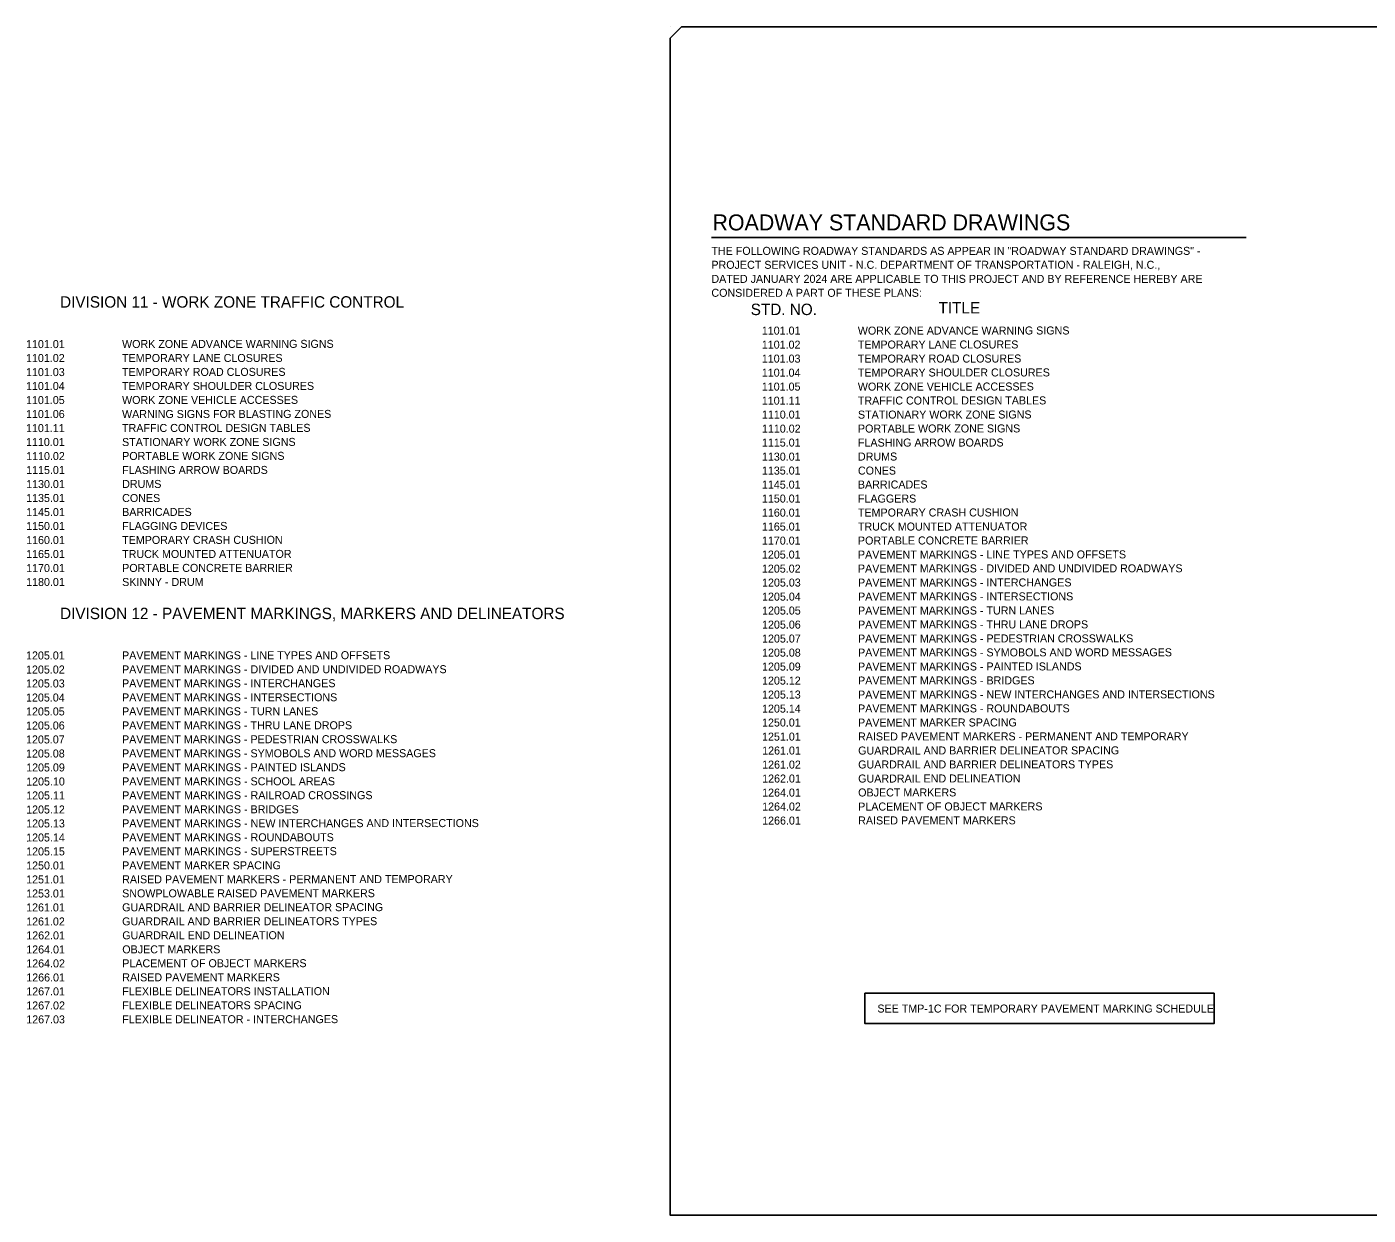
# Model space of a CAD drawing. Extents: x 2486454 to 2490507, y 369321 to 372999.
# Drawn here: x 2486454 to 2487627, y 370218 to 371258 of the extents above; entities that cross this region are included whole.
import ezdxf

# ---------------------------------------------------------------- set-up
doc = ezdxf.new("R2010")
doc.units = 0
for name, color, linetype in [('Scratch_Level_3', 7, 'Continuous'), ('TC SHEET BORDER LINE THIN', 7, 'Continuous'), ('TC SHEET LAYOUT SHAPE', 7, 'Continuous'), ('TC SHEET TEXT', 7, 'Continuous')]:
    doc.layers.add(name, color=color, linetype=linetype)

msp = doc.modelspace()

# ---------------------------------------------------------------- linework, layer by layer
at = {"layer": 'Scratch_Level_3'}
msp.add_line((2487016.6, 371258.3), (2487016.6, 371258.3), dxfattribs=at)
at = {"layer": 'TC SHEET BORDER LINE THIN'}
msp.add_line((2487052.9, 371074), (2487520.6, 371074), dxfattribs=at)
at = {"layer": 'TC SHEET LAYOUT SHAPE'}
msp.add_lwpolyline([(2487016.6, 370666.8), (2487016.6, 370976.2), (2487016.6, 371248.3), (2487026.6, 371258.3), (2487469.6, 371258.3), (2487940.6, 371258.3), (2488261.6, 371258.3), (2488261.6, 371178.3), (2488346.6, 371178.3), (2488346.6, 371226.3), (2488506.6, 371226.3), (2488506.6, 370891.3), (2488506.6, 370612.1), (2488506.6, 370360.8), (2487778.4, 370360.8), (2487778.4, 370218.3), (2487608.9, 370218.3), (2487256.1, 370218.3), (2487016.6, 370218.3)], close=True, dxfattribs=at)
at = {"layer": 'TC SHEET TEXT'}
msp.add_lwpolyline([(2487187, 370412.5), (2487492.4, 370412.5), (2487492.4, 370386), (2487187, 370386)], close=True, dxfattribs=at)

# ---------------------------------------------------------------- texts
for s, height, rotation, p in [('ROADWAY STANDARD DRAWINGS', 13.999, 0.0001, (2487053.6, 371080.1)), ('THE FOLLOWING ROADWAY STANDARDS AS APPEAR IN "ROADWAY STANDARD DRAWINGS" - ', 7, 0, (2487052.7, 371058.7)), ('PROJECT SERVICES UNIT - N.C. DEPARTMENT OF TRANSPORTATION - RALEIGH, N.C.,', 7, 0, (2487052.7, 371046.5)), ('DATED JANUARY 2024 ARE APPLICABLE TO THIS PROJECT AND BY REFERENCE HEREBY ARE', 7, 0, (2487052.7, 371034.2)), ('DIVISION 11 - WORK ZONE TRAFFIC CONTROL', 10, 0.0001, (2486482.9, 371012.5)), ('CONSIDERED A PART OF THESE PLANS:', 7, 0, (2487052.7, 371022)), ('STD. NO.', 10, 0.0001, (2487087.1, 371006)), ('TITLE', 10, 0.0001, (2487251.4, 371007.4)), ('1101.01', 7, 0.0403, (2487096.8, 370988.9)), ('WORK ZONE ADVANCE WARNING SIGNS', 7, 0.0403, (2487180.8, 370988.9)), ('1101.01', 7, 0.0403, (2486453.1, 370977.1)), ('WORK ZONE ADVANCE WARNING SIGNS', 7, 0.0403, (2486537.1, 370977.2)), ('1101.02', 7, 0.0403, (2487096.8, 370976.6)), ('TEMPORARY LANE CLOSURES', 7, 0.0403, (2487180.8, 370976.7)), ('1101.02', 7, 0.0403, (2486453.1, 370964.9)), ('TEMPORARY LANE CLOSURES', 7, 0.0403, (2486537.1, 370964.9)), ('1101.03', 7, 0.0403, (2487096.8, 370964.4)), ('TEMPORARY ROAD CLOSURES', 7, 0.0403, (2487180.8, 370964.4)), ('1101.03', 7, 0.0403, (2486453.1, 370952.6)), ('TEMPORARY ROAD CLOSURES', 7, 0.0403, (2486537.1, 370952.7)), ('1101.04', 7, 0.0403, (2487096.8, 370952.1)), ('TEMPORARY SHOULDER CLOSURES', 7, 0.0403, (2487180.8, 370952.2)), ('1101.04', 7, 0.0403, (2486453.1, 370940.4)), ('TEMPORARY SHOULDER CLOSURES', 7, 0.0403, (2486537.1, 370940.4)), ('1101.05', 7, 0.0403, (2487096.8, 370939.9)), ('WORK ZONE VEHICLE ACCESSES', 7, 0.0403, (2487180.8, 370939.9)), ('1101.05', 7, 0.0403, (2486453.1, 370928.1)), ('WORK ZONE VEHICLE ACCESSES', 7, 0.0403, (2486537.1, 370928.2)), ('1101.11', 7, 0.0403, (2487096.8, 370927.6)), ('TRAFFIC CONTROL DESIGN TABLES', 7, 0.0403, (2487180.8, 370927.7)), ('1101.06', 7, 0.0403, (2486453.1, 370915.9)), ('WARNING SIGNS FOR BLASTING ZONES', 7, 0.0403, (2486537.1, 370915.9)), ('1110.01', 7, 0.0403, (2487096.9, 370915.4)), ('STATIONARY WORK ZONE SIGNS', 7, 0.0403, (2487180.9, 370915.4)), ('1101.11', 7, 0.0403, (2486453.1, 370903.6)), ('TRAFFIC CONTROL DESIGN TABLES', 7, 0.0403, (2486537.1, 370903.7)), ('1110.02', 7, 0.0403, (2487096.9, 370903.1)), ('PORTABLE WORK ZONE SIGNS', 7, 0.0403, (2487180.9, 370903.2)), ('1110.01', 7, 0.0403, (2486453.1, 370891.4)), ('STATIONARY WORK ZONE SIGNS', 7, 0.0403, (2486537.1, 370891.4)), ('1115.01', 7, 0.0403, (2487096.9, 370890.9)), ('FLASHING ARROW BOARDS', 7, 0.0403, (2487180.9, 370890.9)), ('1110.02', 7, 0.0403, (2486453.2, 370879.1)), ('PORTABLE WORK ZONE SIGNS', 7, 0.0403, (2486537.2, 370879.2)), ('1130.01', 7, 0.0403, (2487096.9, 370878.6)), ('DRUMS ', 7, 0.0403, (2487180.9, 370878.7)), ('1115.01', 7, 0.0403, (2486453.2, 370866.9)), ('FLASHING ARROW BOARDS', 7, 0.0403, (2486537.2, 370866.9)), ('1135.01', 7, 0.0403, (2487096.9, 370866.4)), ('CONES', 7, 0.0403, (2487180.9, 370866.4)), ('1130.01', 7, 0.0403, (2486453.2, 370854.6)), ('DRUMS ', 7, 0.0403, (2486537.2, 370854.7)), ('1145.01', 7, 0.0403, (2487096.9, 370854.1)), ('BARRICADES', 7, 0.0403, (2487180.9, 370854.2)), ('1135.01', 7, 0.0403, (2486453.2, 370842.4)), ('CONES', 7, 0.0403, (2486537.2, 370842.4)), ('1150.01', 7, 0.0403, (2487096.9, 370841.9)), ('FLAGGERS', 7, 0.0403, (2487180.9, 370841.9)), ('1145.01', 7, 0.0403, (2486453.2, 370830.1)), ('BARRICADES', 7, 0.0403, (2486537.2, 370830.2)), ('1160.01', 7, 0.0403, (2487096.9, 370829.6)), ('TEMPORARY CRASH CUSHION ', 7, 0.0403, (2487180.9, 370829.7)), ('1150.01', 7, 0.0403, (2486453.2, 370817.9)), ('FLAGGING DEVICES', 7, 0.0403, (2486537.2, 370817.9)), ('1165.01', 7, 0.0403, (2487096.9, 370817.4)), ('TRUCK MOUNTED ATTENUATOR', 7, 0.0403, (2487180.9, 370817.4)), ('1160.01', 7, 0.0403, (2486453.2, 370805.6)), ('TEMPORARY CRASH CUSHION ', 7, 0.0403, (2486537.2, 370805.7)), ('1170.01', 7, 0.0403, (2487096.9, 370805.1)), ('PORTABLE CONCRETE BARRIER', 7, 0.0403, (2487180.9, 370805.2)), ('1165.01', 7, 0.0403, (2486453.2, 370793.4)), ('TRUCK MOUNTED ATTENUATOR', 7, 0.0403, (2486537.2, 370793.4)), ('1205.01', 7, 0.0403, (2487096.9, 370792.9)), ('PAVEMENT MARKINGS - LINE TYPES AND OFFSETS', 7, 0.0403, (2487180.9, 370792.9)), ('1170.01', 7, 0.0403, (2486453.2, 370781.1)), ('PORTABLE CONCRETE BARRIER ', 7, 0.0403, (2486537.2, 370781.2)), ('1205.02', 7, 0.0403, (2487096.9, 370780.6)), ('PAVEMENT MARKINGS - DIVIDED AND UNDIVIDED ROADWAYS', 7, 0.0403, (2487180.9, 370780.7)), ('1180.01', 7, 0.0403, (2486453.2, 370768.9)), ('SKINNY - DRUM', 7, 0.0403, (2486537.2, 370768.9)), ('1205.03', 7, 0.0403, (2487097, 370768.4)), ('PAVEMENT MARKINGS - INTERCHANGES', 7, 0.0403, (2487181, 370768.4)), ('1205.04', 7, 0.0403, (2487097, 370756.1)), ('PAVEMENT MARKINGS - INTERSECTIONS', 7, 0.0403, (2487181, 370756.2)), ('DIVISION 12 - PAVEMENT MARKINGS, MARKERS AND DELINEATORS', 10, 0.0001, (2486482.9, 370739.9)), ('1205.05', 7, 0.0403, (2487097, 370743.9)), ('PAVEMENT MARKINGS - TURN LANES', 7, 0.0403, (2487181, 370743.9)), ('1205.06', 7, 0.0403, (2487097, 370731.6)), ('PAVEMENT MARKINGS - THRU LANE DROPS', 7, 0.0403, (2487181, 370731.7)), ('1205.07', 7, 0.0403, (2487097, 370719.4)), ('PAVEMENT MARKINGS - PEDESTRIAN CROSSWALKS', 7, 0.0403, (2487181, 370719.4)), ('1205.08', 7, 0.0403, (2487097, 370707.1)), ('PAVEMENT MARKINGS - SYMOBOLS AND WORD MESSAGES', 7, 0.0403, (2487181, 370707.2)), ('1205.01', 7, 0.0403, (2486453.1, 370704.6)), ('PAVEMENT MARKINGS - LINE TYPES AND OFFSETS', 7, 0.0403, (2486537.1, 370704.7)), ('1205.09', 7, 0.0403, (2487097, 370694.9)), ('PAVEMENT MARKINGS - PAINTED ISLANDS', 7, 0.0403, (2487181, 370694.9)), ('1205.02', 7, 0.0403, (2486453.1, 370692.3)), ('PAVEMENT MARKINGS - DIVIDED AND UNDIVIDED ROADWAYS', 7, 0.0403, (2486537.1, 370692.4)), ('1205.03', 7, 0.0403, (2486453.1, 370680.1)), ('PAVEMENT MARKINGS - INTERCHANGES', 7, 0.0403, (2486537.1, 370680.2)), ('1205.12', 7, 0.0403, (2487097, 370682.6)), ('PAVEMENT MARKINGS - BRIDGES', 7, 0.0403, (2487181, 370682.7)), ('1205.04', 7, 0.0403, (2486453.1, 370667.8)), ('PAVEMENT MARKINGS - INTERSECTIONS', 7, 0.0403, (2486537.1, 370667.9)), ('1205.13', 7, 0.0403, (2487097, 370670.4)), ('PAVEMENT MARKINGS - NEW INTERCHANGES AND INTERSECTIONS', 7, 0.0403, (2487181, 370670.4)), ('1205.05', 7, 0.0403, (2486453.1, 370655.6)), ('PAVEMENT MARKINGS - TURN LANES', 7, 0.0403, (2486537.1, 370655.7)), ('1205.14', 7, 0.0403, (2487097, 370658.1)), ('PAVEMENT MARKINGS - ROUNDABOUTS', 7, 0.0403, (2487181, 370658.2)), ('1205.06', 7, 0.0403, (2486453.1, 370643.3)), ('PAVEMENT MARKINGS - THRU LANE DROPS', 7, 0.0403, (2486537.1, 370643.4)), ('1250.01', 7, 0.0403, (2487097, 370645.9)), ('PAVEMENT MARKER SPACING', 7, 0.0403, (2487181, 370645.9)), ('1205.07', 7, 0.0403, (2486453.1, 370631.1)), ('PAVEMENT MARKINGS - PEDESTRIAN CROSSWALKS', 7, 0.0403, (2486537.1, 370631.2)), ('1251.01', 7, 0.0403, (2487097, 370633.6)), ('RAISED PAVEMENT MARKERS - PERMANENT AND TEMPORARY', 7, 0.0403, (2487181, 370633.7)), ('1205.08', 7, 0.0403, (2486453.1, 370618.8)), ('PAVEMENT MARKINGS - SYMOBOLS AND WORD MESSAGES', 7, 0.0403, (2486537.1, 370618.9)), ('1261.01', 7, 0.0403, (2487097.1, 370621.4)), ('GUARDRAIL AND BARRIER DELINEATOR SPACING', 7, 0.0403, (2487181.1, 370621.4)), ('1205.09', 7, 0.0403, (2486453.2, 370606.6)), ('PAVEMENT MARKINGS - PAINTED ISLANDS', 7, 0.0403, (2486537.2, 370606.7)), ('1261.02', 7, 0.0403, (2487097.1, 370609.1)), ('GUARDRAIL AND BARRIER DELINEATORS TYPES', 7, 0.0403, (2487181.1, 370609.2)), ('1205.10', 7, 0.0403, (2486453.2, 370594.3)), ('PAVEMENT MARKINGS - SCHOOL AREAS', 7, 0.0403, (2486537.2, 370594.4)), ('1262.01', 7, 0.0403, (2487097.1, 370596.9)), ('GUARDRAIL END DELINEATION', 7, 0.0403, (2487181.1, 370596.9)), ('1205.11', 7, 0.0403, (2486453.2, 370582.1)), ('PAVEMENT MARKINGS - RAILROAD CROSSINGS', 7, 0.0403, (2486537.2, 370582.2)), ('1264.01', 7, 0.0403, (2487097.1, 370584.6)), ('OBJECT MARKERS', 7, 0.0403, (2487181.1, 370584.7)), ('1205.12', 7, 0.0403, (2486453.2, 370569.8)), ('PAVEMENT MARKINGS - BRIDGES', 7, 0.0403, (2486537.2, 370569.9)), ('1264.02', 7, 0.0403, (2487097.1, 370572.4)), ('PLACEMENT OF OBJECT MARKERS', 7, 0.0403, (2487181.1, 370572.4)), ('1205.13', 7, 0.0403, (2486453.2, 370557.6)), ('PAVEMENT MARKINGS - NEW INTERCHANGES AND INTERSECTIONS', 7, 0.0403, (2486537.2, 370557.7)), ('1266.01', 7, 0.0403, (2487097.1, 370560.1)), ('RAISED PAVEMENT MARKERS', 7, 0.0403, (2487181.1, 370560.2)), ('1205.14', 7, 0.0403, (2486453.2, 370545.3)), ('PAVEMENT MARKINGS - ROUNDABOUTS', 7, 0.0403, (2486537.2, 370545.4)), ('1205.15', 7, 0.0403, (2486453.2, 370533.1)), ('PAVEMENT MARKINGS - SUPERSTREETS', 7, 0.0403, (2486537.2, 370533.2)), ('1250.01', 7, 0.0403, (2486453.2, 370520.8)), ('PAVEMENT MARKER SPACING', 7, 0.0403, (2486537.2, 370520.9)), ('1251.01', 7, 0.0403, (2486453.2, 370508.6)), ('RAISED PAVEMENT MARKERS - PERMANENT AND TEMPORARY', 7, 0.0403, (2486537.2, 370508.7)), ('1253.01', 7, 0.0403, (2486453.2, 370496.3)), ('SNOWPLOWABLE RAISED PAVEMENT MARKERS', 7, 0.0403, (2486537.2, 370496.4)), ('1261.01', 7, 0.0403, (2486453.2, 370484.1)), ('GUARDRAIL AND BARRIER DELINEATOR SPACING', 7, 0.0403, (2486537.2, 370484.2)), ('1261.02', 7, 0.0403, (2486453.2, 370471.8)), ('GUARDRAIL AND BARRIER DELINEATORS TYPES', 7, 0.0403, (2486537.2, 370471.9)), ('1262.01', 7, 0.0403, (2486453.3, 370459.6)), ('GUARDRAIL END DELINEATION', 7, 0.0403, (2486537.3, 370459.7)), ('1264.01', 7, 0.0403, (2486453.3, 370447.3)), ('OBJECT MARKERS', 7, 0.0403, (2486537.3, 370447.4)), ('1264.02', 7, 0.0403, (2486453.3, 370435.1)), ('PLACEMENT OF OBJECT MARKERS', 7, 0.0403, (2486537.3, 370435.2)), ('1266.01', 7, 0.0403, (2486453.3, 370422.8)), ('RAISED PAVEMENT MARKERS', 7, 0.0403, (2486537.3, 370422.9)), ('1267.01', 7, 0.0403, (2486453.3, 370410.6)), ('FLEXIBLE DELINEATORS INSTALLATION', 7, 0.0403, (2486537.3, 370410.7)), ('1267.02', 7, 0.0403, (2486453.3, 370398.3)), ('FLEXIBLE DELINEATORS SPACING', 7, 0.0403, (2486537.3, 370398.4)), ('1267.03', 7, 0.0403, (2486453.3, 370386.1)), ('FLEXIBLE DELINEATOR - INTERCHANGES', 7, 0.0403, (2486537.3, 370386.2))]:
    msp.add_text(s, height=height, rotation=rotation, dxfattribs=at).set_placement(p)
msp.add_text('SEE TMP-1C FOR TEMPORARY PAVEMENT MARKING SCHEDULE', height=7, dxfattribs=at).set_placement((2487197.9, 370395.6))

doc.saveas('drawing.dxf')
